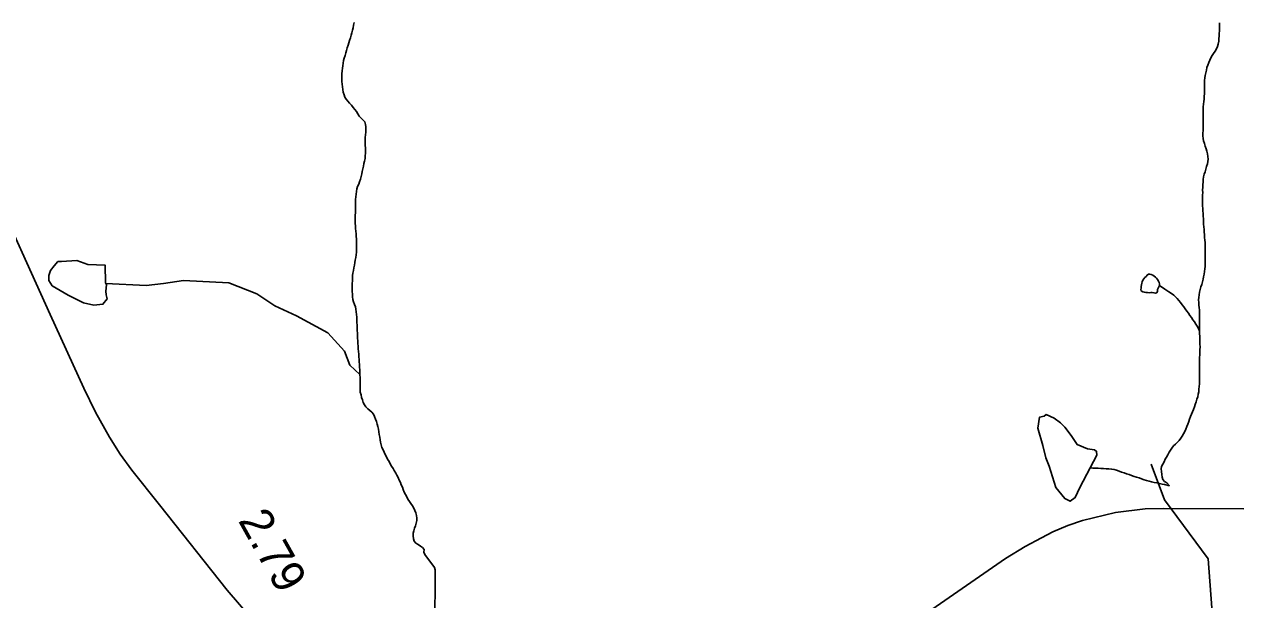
# Model space of a CAD drawing. Extents: x 1950930 to 2061844, y 904556 to 1017002.
# Drawn here: x 1994978 to 1999576, y 925314 to 927499 of the extents above; entities that cross this region are included whole.
import ezdxf

# ---------------------------------------------------------------- set-up
doc = ezdxf.new("R2010")
doc.units = 0
for name, color, linetype in [('Exist Hydrographic Creek Single Shore', 7, 'Continuous'), ('Exist Hydrographic Misc Water Feature', 7, 'Continuous'), ('Exist Road Primary US Structure Standard Bridge CELL', 7, 'Continuous'), ('Exist Road Secondary Type 51 Attributed', 7, 'Continuous')]:
    doc.layers.add(name, color=color, linetype=linetype)

msp = doc.modelspace()

# ---------------------------------------------------------------- linework, layer by layer
at = {"layer": 'Exist Hydrographic Creek Single Shore'}
for points in [[(1996229, 927505.6), (1996226.9, 927495.8), (1996224.9, 927485.9), (1996222.6, 927476.9), (1996220.2, 927467.2), (1996217.3, 927457.4), (1996214.8, 927447.7), (1996211.8, 927438), (1996208.9, 927428.3), (1996206.2, 927419.4), (1996202.7, 927409.4), (1996199.9, 927399.6), (1996197.6, 927390.7), (1996194.7, 927381), (1996191.7, 927370.8), (1996189.2, 927361.1), (1996187.2, 927351.2), (1996185.7, 927341.8), (1996184.5, 927331.8), (1996183.7, 927322.2), (1996182.6, 927311.3), (1996182.4, 927301.7), (1996182.4, 927291.6), (1996182.9, 927281.7), (1996183.7, 927271.9), (1996184.9, 927261.1), (1996186.3, 927251.6), (1996188, 927241.5), (1996190.6, 927231.4), (1996194.1, 927222.3), (1996199.3, 927214.3), (1996205.6, 927206.8), (1996212, 927199.4), (1996218.7, 927191.4), (1996225.5, 927183.1), (1996231.4, 927175.7), (1996237.4, 927167.5), (1996242.7, 927159.4), (1996248.5, 927150.8), (1996254.6, 927143.4), (1996261.8, 927135.8), (1996269, 927128.2), (1996272.7, 927119.1), (1996273.7, 927110.1), (1996273.3, 927100.3), (1996272.9, 927089.5), (1996272, 927079.8), (1996271, 927069.1), (1996270.8, 927059.3), (1996270.8, 927049.2), (1996271.2, 927039.8), (1996272, 927028.7), (1996272, 927018.9), (1996271.6, 927009.3), (1996271.4, 926999.6), (1996270.2, 926989.6), (1996268.6, 926979.8), (1996266.1, 926969.9), (1996264.5, 926960.1), (1996262.4, 926950.2), (1996259.7, 926940.5), (1996257.7, 926930.7), (1996255.2, 926920.8), (1996252.8, 926911.1), (1996249.9, 926901.3), (1996246.4, 926892.6), (1996242.1, 926882.7), (1996239.4, 926873.8), (1996237.8, 926863.9), (1996236.6, 926853.9), (1996236, 926843.4), (1996234.7, 926833.5), (1996234.5, 926823.8), (1996234.5, 926814), (1996233.7, 926804), (1996233.7, 926793.5), (1996233.7, 926783.7), (1996232.9, 926773.7), (1996232.9, 926764), (1996233.5, 926754.1), (1996233.3, 926743.1), (1996233.9, 926733.4), (1996234.3, 926723.6), (1996235.1, 926713.7), (1996236.2, 926703.8), (1996236.6, 926694), (1996237.4, 926683.4), (1996237.4, 926673.5), (1996238.4, 926663.7), (1996238.4, 926653.9), (1996237.6, 926643.9), (1996237.6, 926633.3), (1996236.8, 926623.4), (1996235.1, 926613.9), (1996233.5, 926603.9), (1996231.9, 926594.1), (1996229.8, 926584.2), (1996228.2, 926574.4), (1996226.1, 926564.5)], [(1996226.1, 926564.5), (1996224.5, 926554.6), (1996223.2, 926545.1), (1996222.4, 926535.4), (1996222.4, 926524.5), (1996221.6, 926514.8), (1996221.6, 926504.7), (1996221.8, 926494.9), (1996221.6, 926484.4), (1996222.2, 926474.6), (1996222.6, 926464.8), (1996224.5, 926454.7), (1996227.1, 926445.8), (1996230, 926435.7), (1996233.7, 926426.5), (1996236, 926416.9), (1996237.2, 926407), (1996238.2, 926397.1), (1996238.8, 926386.5), (1996239.4, 926376.6), (1996239.4, 926366.9), (1996240.1, 926357), (1996240.5, 926346.9), (1996240.9, 926337), (1996241.7, 926326.4), (1996241.7, 926316.6), (1996242.1, 926306.8), (1996243.1, 926296.9), (1996243.5, 926287.1), (1996244.2, 926277.3), (1996244.4, 926266.7), (1996245.8, 926256.8), (1996246.2, 926246.9), (1996246.6, 926236.7), (1996247.6, 926226.8), (1996248.5, 926217.4), (1996248.9, 926207.1), (1996249.9, 926196.9), (1996250.3, 926186.6), (1996250.3, 926176.9), (1996250.7, 926169.5)], [(1996250.7, 926169.5), (1996212.4, 926204.6), (1996192.1, 926258.4), (1996129.3, 926328), (1996010.8, 926392.7), (1995928.4, 926430.3), (1995860.3, 926475.2), (1995753.7, 926517), (1995581.8, 926525.7), (1995506, 926514.8), (1995440.4, 926507.8), (1995287.2, 926514.4)], [(1996250.7, 926169.5), (1996251.3, 926157.3), (1996251.3, 926147.5), (1996251.3, 926136.6), (1996251.7, 926126.8), (1996251.7, 926117), (1996252.4, 926102.4), (1996255.2, 926092.1), (1996257.5, 926082.5), (1996260.6, 926072.6), (1996263.6, 926063.3), (1996267.7, 926054.5), (1996273.1, 926046), (1996280.5, 926039.2), (1996288.2, 926032.3), (1996295.6, 926026), (1996302.2, 926018.5), (1996306.5, 926009.3), (1996310.2, 926000.2), (1996313.5, 925990.3), (1996316.1, 925980.2), (1996318.4, 925971.3), (1996321.1, 925961.2), (1996322.9, 925951.5), (1996324.1, 925941.7), (1996326, 925931.6), (1996327.4, 925920.9), (1996329.5, 925912.1), (1996331.5, 925901.9), (1996334.6, 925892.2), (1996338.7, 925883.1), (1996342.6, 925873.9), (1996346.7, 925865.5), (1996351.6, 925856.3), (1996356.1, 925847.5), (1996361.5, 925839), (1996366.2, 925829.7), (1996371.3, 925821.6), (1996376.6, 925812.3), (1996381.1, 925804.3), (1996386.5, 925795), (1996391.4, 925787), (1996395.9, 925777.8), (1996400.2, 925768.5), (1996404.3, 925759.4), (1996407.8, 925750.4), (1996411.9, 925741.3), (1996415.4, 925732.1), (1996419.3, 925722.2), (1996423.4, 925713.9), (1996428.3, 925704.7), (1996433.2, 925696.6), (1996438.6, 925687.2), (1996444.1, 925679.1), (1996449.8, 925670.5), (1996454.8, 925662.4), (1996459.3, 925653.3), (1996462.7, 925644.2), (1996465.4, 925634), (1996467.3, 925624.5), (1996467.3, 925614.7), (1996464.8, 925604.9), (1996461.3, 925594.9), (1996457.8, 925586.1), (1996455, 925576.4), (1996452.9, 925566.6), (1996452.5, 925556.5), (1996453.7, 925545.7), (1996456.4, 925536.8), (1996462.7, 925529.3), (1996471.8, 925524.3), (1996480.6, 925518.2), (1996488.4, 925512.4), (1996494.9, 925504.9), (1996493.7, 925495), (1996496.8, 925486.1), (1996534.2, 925436.7), (1996536.7, 925427.9), (1996535.8, 925356.4)], [(1996535.8, 925356.4), (1996534.8, 925273.6)]]:
    msp.add_lwpolyline(points, dxfattribs=at)
at = {"layer": 'Exist Hydrographic Misc Water Feature'}
msp.add_line((1999434.8, 926334.5), (1999434.8, 926329.2), dxfattribs=at)
for points in [[(1999510.6, 927504.4), (1999510.8, 927494.7), (1999510.8, 927484.9)], [(1999510.8, 927484.9), (1999510.4, 927474.8), (1999509.6, 927464.4), (1999509.2, 927454.3), (1999508.8, 927444.6), (1999508, 927434.6), (1999506.1, 927423.9), (1999503.5, 927415), (1999499, 927406), (1999494, 927397.4), (1999488.7, 927388.4), (1999483.2, 927380.3), (1999478.2, 927371.3), (1999473.7, 927362.3), (1999469.8, 927353.6), (1999466.1, 927344.4), (1999463.3, 927334.6), (1999461.2, 927324.8), (1999458.8, 927315), (1999457.1, 927305.2), (1999455.5, 927295.7), (1999454.3, 927285.7), (1999453.6, 927274.8), (1999453.8, 927265.1), (1999453.4, 927255.4), (1999454, 927245.5), (1999454, 927235.4), (1999453.2, 927225.7), (1999452.2, 927215), (1999451.6, 927205.3), (1999450.4, 927195.4), (1999449.5, 927185.7), (1999449.1, 927175.7), (1999448.3, 927165.2), (1999448.3, 927155.1), (1999448.3, 927145.4), (1999448.3, 927135.6), (1999448.9, 927125.8), (1999448.9, 927116), (1999448.7, 927105.1), (1999448.9, 927095.3), (1999448.1, 927085.7), (1999448.1, 927075.5), (1999449.1, 927065.7), (1999450.8, 927056.1), (1999453.4, 927046), (1999456.5, 927036.2), (1999460, 927026.3), (1999463.1, 927017.3), (1999465.7, 927007.1), (1999467, 926997.2), (1999467.8, 926987.4), (1999466.8, 926978.5), (1999465.1, 926968.7), (1999462.2, 926959), (1999459, 926948.9), (1999456.1, 926939.3), (1999453.2, 926929.5), (1999450.6, 926919.8), (1999449.3, 926909.9), (1999448.3, 926900.2), (1999447.5, 926890.2), (1999447.5, 926880.4), (1999446.9, 926869.6), (1999447.1, 926859.8), (1999446.7, 926850.2), (1999446.9, 926840.4), (1999446.9, 926830.3), (1999446.7, 926819.7), (1999446.9, 926810), (1999447.3, 926800.1), (1999447.7, 926790.3), (1999448.7, 926780.5), (1999449.1, 926770.6), (1999449.9, 926760), (1999450.4, 926750.1), (1999450.8, 926740), (1999451.8, 926730), (1999452.2, 926720.3), (1999453.2, 926710.3), (1999453.6, 926700.6), (1999454.5, 926689.9), (1999455.3, 926680), (1999455.9, 926670.1), (1999456.3, 926660.4), (1999456.3, 926650.7), (1999456.5, 926640.9), (1999456.7, 926629.9), (1999456.9, 926620.1), (1999456.9, 926610.4), (1999456.5, 926600.6), (1999456.1, 926589.8), (1999456.1, 926580), (1999454.9, 926570.1), (1999453.6, 926560.5), (1999452.4, 926550.6), (1999450.8, 926540.7), (1999448.3, 926530.9), (1999445.8, 926521.2), (1999443.4, 926511.3)], [(1995287.2, 926514.4), (1995285.5, 926517.6), (1995285.1, 926584.1), (1995218.9, 926587.3), (1995176.9, 926602.7), (1995118.8, 926598.1), (1995105.3, 926598.5), (1995091.2, 926582.4), (1995077, 926564.6), (1995071.3, 926545.7), (1995071.5, 926526.1), (1995084, 926506.4), (1995144.3, 926470.4), (1995202.3, 926441.3), (1995242.1, 926433.2), (1995276.1, 926435.8), (1995292.3, 926456.1), (1995288, 926471.7), (1995287.8, 926485.5), (1995289.8, 926510), (1995287.2, 926514.4)], [(1999283.9, 926507.2), (1999283, 926513), (1999281.8, 926518.9), (1999278.9, 926523.8), (1999275.7, 926529.6), (1999272.2, 926534.5), (1999267.9, 926538.9), (1999262.7, 926542.1), (1999257.6, 926546.1), (1999252.1, 926549), (1999246.3, 926550.6), (1999241.2, 926549.8), (1999236.5, 926546.9), (1999232.2, 926541.9), (1999228.1, 926537.2), (1999224.2, 926532.1), (1999220.5, 926527.4), (1999218.2, 926521.7), (1999216.4, 926516.3), (1999215, 926510.4), (1999213.9, 926503.6), (1999213.3, 926497.3), (1999213.1, 926491.5), (1999214.3, 926486.5), (1999219.5, 926483.3), (1999226, 926481.5), (1999231.8, 926480.7), (1999237.7, 926480.6), (1999243.9, 926480), (1999250, 926480.7), (1999256, 926480.6), (1999262.5, 926478.8), (1999268.7, 926477.9), (1999273.2, 926479.7), (1999275.4, 926485.4), (1999276.1, 926491.7), (1999278.3, 926497.5), (1999283.9, 926507.2)], [(1999283.9, 926507.2), (1999303.9, 926493.6), (1999318.5, 926483.6), (1999328.4, 926476.9), (1999338, 926470.2), (1999345.2, 926462.6), (1999350.7, 926458.1), (1999356.6, 926449.9), (1999362.6, 926442.4), (1999369.4, 926434.1), (1999375.3, 926426.7), (1999381, 926418.1), (1999387, 926409.9), (1999393.1, 926401.7), (1999398.7, 926393.9), (1999404.2, 926385.8), (1999410, 926377.2), (1999415.5, 926369.1), (1999420.8, 926361), (1999426.2, 926352.4), (1999430.9, 926344.4), (1999434.8, 926334.5)], [(1999443.4, 926511.3), (1999440.5, 926501.7), (1999438.1, 926491.9), (1999435.6, 926482.1), (1999434, 926472.3), (1999432.3, 926462.3), (1999431.5, 926452.3), (1999431.9, 926442.5), (1999432.3, 926432.7), (1999433.7, 926423.2), (1999435.6, 926413.1), (1999434.8, 926334.5)], [(1999434.8, 926329.2), (1999435.6, 926324.2), (1999436, 926314.5), (1999436, 926303.9), (1999436.4, 926294.1), (1999436.6, 926284.3), (1999437, 926274.5), (1999436.4, 926263.6), (1999436.6, 926253.9), (1999435.8, 926244.3), (1999435.4, 926234.2), (1999435.6, 926224.5), (1999434.6, 926213.6), (1999434.6, 926203.9), (1999435.2, 926194), (1999435.6, 926184.3), (1999435.2, 926174.5), (1999435.2, 926164.4), (1999434.8, 926153.9), (1999435, 926144.2), (1999434.6, 926134), (1999434, 926123.6), (1999433.1, 926113.5), (1999431.9, 926103.6), (1999430.5, 926094.2), (1999428.2, 926084.3), (1999425.5, 926075.4), (1999422.3, 926065.3), (1999419.2, 926055.6), (1999415.7, 926046.8), (1999411.8, 926036.8), (1999408.7, 926028), (1999405, 926018.4), (1999400.9, 926009.3), (1999397.7, 925999.6), (1999394, 925990.5), (1999391.1, 925980.8), (1999387.4, 925971.9), (1999383.7, 925962), (1999378.8, 925953.4), (1999374.5, 925944.4), (1999369.6, 925935.3), (1999363.8, 925927.2), (1999358.3, 925919.1), (1999351.3, 925912.6), (1999343.7, 925905.2), (1999337, 925898.1), (1999330.6, 925890.1), (1999325.3, 925882), (1999319.7, 925873.9), (1999314.8, 925864.9), (1999309.5, 925856), (1999305.2, 925847.4), (1999300.7, 925838.2), (1999296.2, 925829.2), (1999291.2, 925820.2), (1999290, 925810.7), (1999290.6, 925800.8), (1999291.6, 925790.1), (1999293.5, 925780.1), (1999296.2, 925771.2), (1999302.7, 925763.7), (1999311.3, 925757.5), (1999321, 925746.7)], [(1999021, 925814.7), (1999045.2, 925863.3), (1999045, 925877.1), (1999037, 925883.2), (1999010.7, 925886.7), (1998970.7, 925904.2), (1998948.4, 925938.1), (1998924, 925969.8), (1998907.8, 925985.6), (1998884, 926003.4), (1998853.7, 926017.4), (1998845.5, 926011.7), (1998827.8, 926007.1), (1998821.7, 925965.5), (1998840.3, 925899.3), (1998852.6, 925853.2), (1998865.3, 925821.6), (1998889.9, 925740), (1998924.2, 925698.2), (1998944.1, 925688.3), (1998964, 925702.3), (1998981.8, 925740.6), (1999021, 925814.7)], [(1999021, 925814.7), (1999031, 925814.3), (1999041.3, 925813.9), (1999050.9, 925813.7), (1999061.4, 925812.9), (1999071.2, 925812.7), (1999081.1, 925811.6), (1999090.9, 925811.3), (1999101.4, 925810.5), (1999110.8, 925808.7), (1999120.6, 925806), (1999129.9, 925802.6), (1999139.5, 925799.1), (1999148.9, 925795.6), (1999158.2, 925792.1), (1999168, 925789.4), (1999177.2, 925786), (1999186.9, 925782.5), (1999196.1, 925779.1), (1999205.7, 925776.4), (1999215.4, 925772.9), (1999224.6, 925769.9), (1999234.2, 925766.8), (1999244.1, 925764.1), (1999253.5, 925762.3), (1999263.3, 925759.5), (1999273.2, 925757.7), (1999283, 925755.7), (1999292.9, 925753), (1999302.7, 925751.1), (1999321, 925746.7)], [(1999283.1, 923848), (1999334.1, 924311.1), (1999434.2, 924578.1), (1999468.2, 924945), (1999501.2, 925029.7), (1999468.2, 925470.1), (1999302.1, 925693.4), (1999252.1, 925829)]]:
    msp.add_lwpolyline(points, dxfattribs=at)
at = {"layer": 'Exist Road Secondary Type 51 Attributed'}
for points in [[(1995888.2, 925186.9), (1995747, 925350.6), (1995490.5, 925674.7), (1995385.7, 925806.3), (1995341.9, 925867.1), (1995301.3, 925932), (1995247.9, 926026.8), (1995203.9, 926117.4), (1995076.5, 926397.5), (1994850.9, 926892.7)], [(1999603.3, 925659.5), (1999299.6, 925661), (1999229.4, 925659.7), (1999116.1, 925645.1), (1998990.8, 925614.7), (1998935.6, 925595.9), (1998878.4, 925571.5), (1998835.4, 925549.8), (1998773.6, 925516.6), (1998699.2, 925471.1), (1998518.8, 925345), (1998223.3, 925140.6)]]:
    msp.add_lwpolyline(points, dxfattribs=at)

# ---------------------------------------------------------------- texts
at = {"layer": 'Exist Road Primary US Structure Standard Bridge CELL'}
msp.add_text('2.79', height=125, rotation=299.1874, dxfattribs=at).set_placement((1995787.3, 925615))

doc.saveas('drawing.dxf')
